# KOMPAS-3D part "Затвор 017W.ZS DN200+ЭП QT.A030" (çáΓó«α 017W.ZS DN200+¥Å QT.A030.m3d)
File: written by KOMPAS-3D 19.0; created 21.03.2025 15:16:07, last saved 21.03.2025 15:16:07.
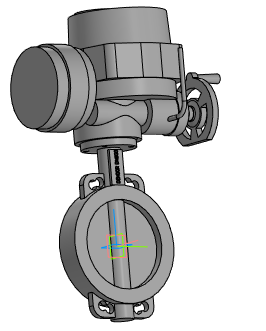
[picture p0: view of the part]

Document properties: Полное имя файла: Затвор 017W.ZS DN200+ЭП QT.A030.a3d

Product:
- Part/product: Затвор 017W.ZS DN200+ЭП QT.A030
    Масса: 134.577

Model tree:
1. Операция без истории:1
